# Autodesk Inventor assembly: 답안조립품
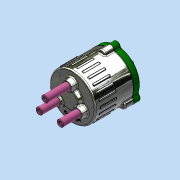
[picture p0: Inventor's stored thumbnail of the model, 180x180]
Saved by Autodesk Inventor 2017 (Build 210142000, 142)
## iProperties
Part Number: 답안조립품
Material: 일반
Document SubType Name: Assembly
Designer: MRC
Author: MRC
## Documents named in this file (15)
- C:\Users\MRC\Desktop\620811V1013\답안조립품.iam
- C:\Users\MRC\Desktop\620811V1013\본체.ipt
- C:\Users\MRC\Desktop\620811V1013\가변스프링1.ipt
- C:\Users\MRC\Desktop\620811V1013\가변스프링2.ipt
- C:\Users\MRC\Desktop\620811V1013\가변스프링3.ipt
- C:\Users\MRC\Desktop\620811V1013\개스킷.ipt
- C:\Users\MRC\Desktop\620811V1013\멈춤링 10x1.ipt
- C:\Users\MRC\Desktop\620811V1013\멈춤링 22x1.2.ipt
- C:\Users\MRC\Desktop\620811V1013\메인 축.ipt
- C:\Users\MRC\Desktop\620811V1013\베어링 NA 4900.ipt
- C:\Users\MRC\Desktop\620811V1013\볼트 M5.ipt
- C:\Users\MRC\Desktop\620811V1013\슬라이드 축.ipt
- C:\Users\MRC\Desktop\620811V1013\오일 실.ipt
- C:\Users\MRC\Desktop\620811V1013\커버.ipt
- C:\Users\MRC\Desktop\620811V1013\판캠.ipt
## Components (4 placed, 4 different names)
1. 가변스프링1:1
2. 가변스프링2:1
3. 가변스프링3:1
4. 개스킷:1
